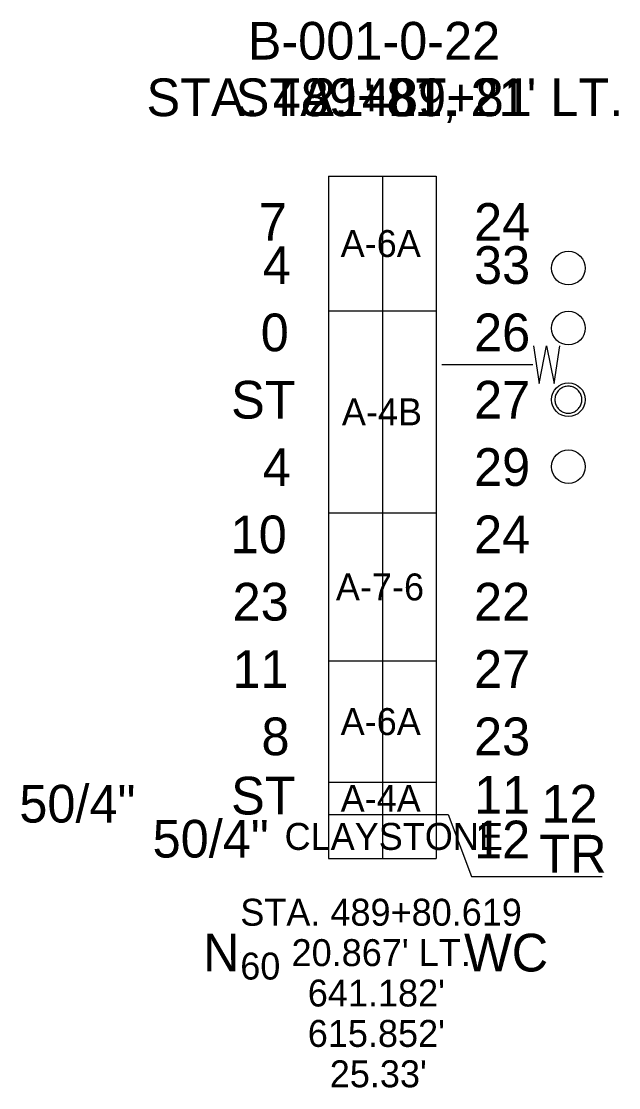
# Model space of a CAD drawing. Extents: x -1.34 to 0.88, y -3.38 to 0.57.
import ezdxf

# ---------------------------------------------------------------- set-up
doc = ezdxf.new("R2010")
doc.units = 0
for name, color, linetype in [('GT_Project_Cells', 7, 'Continuous'), ('GT_Project_Soil_Boring', 7, 'Continuous'), ('GT_Project_Text', 7, 'Continuous'), ('GT_Project_Text_3', 7, 'Continuous'), ('SC_Scratch1', 7, 'Continuous'), ('SC_Scratch2', 7, 'Continuous'), ('SC_Scratch3', 7, 'Continuous')]:
    doc.layers.add(name, color=color, linetype=linetype)

msp = doc.modelspace()

# ---------------------------------------------------------------- linework, layer by layer
at = {"layer": 'GT_Project_Cells'}
msp.add_line((0.5579, -0.7), (0.221, -0.7), dxfattribs=at)
for points in [[(0.5606, -0.6293), (0.5816, -0.7693), (0.6092, -0.6293), (0.6367, -0.7693), (0.6587, -0.6293)], [(0.69, -0.88), (0.6939, -0.8798), (0.6978, -0.8794), (0.7017, -0.8786), (0.7055, -0.8776), (0.7091, -0.8762), (0.7127, -0.8746), (0.7161, -0.8726), (0.7194, -0.8705), (0.7225, -0.868), (0.7254, -0.8654), (0.728, -0.8625), (0.7305, -0.8594), (0.7326, -0.8561), (0.7346, -0.8527), (0.7362, -0.8491), (0.7376, -0.8455), (0.7386, -0.8417), (0.7394, -0.8378), (0.7398, -0.8339), (0.74, -0.83), (0.7398, -0.8261), (0.7394, -0.8222), (0.7386, -0.8183), (0.7376, -0.8145), (0.7362, -0.8109), (0.7346, -0.8073), (0.7326, -0.8039), (0.7305, -0.8006), (0.728, -0.7975), (0.7254, -0.7946), (0.7225, -0.792), (0.7194, -0.7895), (0.7161, -0.7874), (0.7127, -0.7854), (0.7091, -0.7838), (0.7055, -0.7824), (0.7017, -0.7814), (0.6978, -0.7806), (0.6939, -0.7802), (0.69, -0.78), (0.6861, -0.7802), (0.6822, -0.7806), (0.6783, -0.7814), (0.6745, -0.7824), (0.6709, -0.7838), (0.6673, -0.7854), (0.6639, -0.7874), (0.6606, -0.7895), (0.6575, -0.792), (0.6546, -0.7946), (0.652, -0.7975), (0.6495, -0.8006), (0.6474, -0.8039), (0.6454, -0.8073), (0.6438, -0.8109), (0.6424, -0.8145), (0.6414, -0.8183), (0.6406, -0.8222), (0.6402, -0.8261), (0.64, -0.83), (0.6402, -0.8339), (0.6406, -0.8378), (0.6414, -0.8417), (0.6424, -0.8455), (0.6438, -0.8491), (0.6454, -0.8527), (0.6474, -0.8561), (0.6495, -0.8594), (0.652, -0.8625), (0.6546, -0.8654), (0.6575, -0.868), (0.6606, -0.8705), (0.6639, -0.8726), (0.6673, -0.8746), (0.6709, -0.8762), (0.6745, -0.8776), (0.6783, -0.8786), (0.6822, -0.8794), (0.6861, -0.8798), (0.69, -0.88)]]:
    msp.add_lwpolyline(points, dxfattribs=at)
for centre in [(0.69, -0.3413), (0.69, -0.5642), (0.69, -0.83), (0.69, -1.0787)]:
    msp.add_circle(centre, 0.0625, dxfattribs=at)
at = {"layer": 'GT_Project_Soil_Boring'}
for p, q in [((-0.2, 0), (0.2, 0)), ((-0.2, 0), (-0.2, -2.533)), ((0, 0), (0, -2.533)), ((0.2, 0), (0.2, -2.533)), ((-0.2, -0.5), (0.2, -0.5)), ((-0.2, -1.25), (0.2, -1.25)), ((-0.2, -1.8), (0.2, -1.8)), ((-0.2, -2.25), (0.2, -2.25)), ((-0.2, -2.37), (0.2, -2.37)), ((-0.2, -2.533), (0.2, -2.533))]:
    msp.add_line(p, q, dxfattribs=at)
at = {"layer": 'GT_Project_Text'}
for p, q in [((0.2, -2.37), (0.2443, -2.37)), ((-0.5272, -2.883), (-0.5272, -2.883))]:
    msp.add_line(p, q, dxfattribs=at)
msp.add_lwpolyline([(0.2443, -2.37), (0.3304, -2.6001), (0.8155, -2.6001)], dxfattribs=at)

# ---------------------------------------------------------------- texts
for s, height, p in [('B-001-0-22', 0.14, (-0.4996, 0.4329)), ("21' LT.", 0.14, (-0.2769, 0.2229)), ('7', 0.14, (-0.4582, -0.24)), ('24', 0.14, (0.34, -0.24)), ('4', 0.14, (-0.4437, -0.4)), ('33', 0.14, (0.34, -0.4)), ('0', 0.14, (-0.4512, -0.65)), ('26', 0.14, (0.34, -0.65)), ('ST', 0.14, (-0.5611, -0.9)), ('27', 0.14, (0.34, -0.9)), ('4', 0.14, (-0.4437, -1.15)), ('29', 0.14, (0.34, -1.15)), ('10', 0.14, (-0.5629, -1.4)), ('24', 0.14, (0.34, -1.4)), ('23', 0.14, (-0.5555, -1.65)), ('22', 0.14, (0.34, -1.65)), ('11', 0.14, (-0.5562, -1.9)), ('27', 0.14, (0.34, -1.9)), ('8', 0.14, (-0.4485, -2.15)), ('23', 0.14, (0.34, -2.15)), ('50/4"', 0.14, (-1.3467, -2.4)), ('ST', 0.14, (-0.5611, -2.37)), ('11', 0.14, (0.34, -2.367)), ('12', 0.14, (0.59, -2.4)), ('50/4"', 0.14, (-0.8523, -2.53)), ('12', 0.14, (0.34, -2.533)), ('TR', 0.14, (0.582, -2.5855)), ('WC', 0.14, (0.303, -2.953)), ('N', 0.14, (-0.6652, -2.953)), ('60', 0.1, (-0.5272, -2.983))]:
    msp.add_text(s, height=height, dxfattribs=at).set_placement(p)
at = {"layer": 'GT_Project_Text_3'}
msp.add_text('STA. 489+81', height=0.14, dxfattribs=at).set_placement((-0.5439, 0.2229))
at = {"layer": 'SC_Scratch1'}
for s, p in [('A-6A', (-0.1548, -0.3)), ('A-4B', (-0.1503, -0.925)), ('A-7-6', (-0.1725, -1.575)), ('A-6A', (-0.1548, -2.075)), ('A-4A', (-0.1548, -2.36)), ('CLAYSTONE', (-0.3628, -2.5015))]:
    msp.add_text(s, height=0.1, dxfattribs=at).set_placement(p)
at = {"layer": 'SC_Scratch2'}
for s, p in [('STA. 489+80.619', (-0.5271, -2.783)), ("20.867' LT.", (-0.3368, -2.933)), ("641.182'", (-0.2767, -3.083)), ("615.852'", (-0.2767, -3.233)), ("25.33'", (-0.1952, -3.383))]:
    msp.add_text(s, height=0.1, dxfattribs=at).set_placement(p)
at = {"layer": 'SC_Scratch3'}
msp.add_text("STA. 489+81, 21' LT.", height=0.14, dxfattribs=at).set_placement((-0.875, 0.2229))

doc.saveas('drawing.dxf')
